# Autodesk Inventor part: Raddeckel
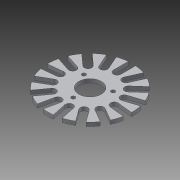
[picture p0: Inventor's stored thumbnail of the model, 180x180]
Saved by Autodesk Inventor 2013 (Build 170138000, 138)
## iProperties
Created: 2012-07
Part Number: Raddeckel
Material: Aluminium 6061
Document SubType Name: Modeling
Designer: rYan
Mass: 5.30786 g
Surface Area: 28.6162 cm^2
Volume: 1.95862 cm^3
Density: 2.71 g/cm^3
Author: rYan
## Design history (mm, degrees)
sketch "Skizze1"
  geometry: C1 r 22.5 at (0, 0); A1 r 22.5 centre (0, 0) between (2, 22.411) and (-2, 22.411) reference; 1 further point
  constraints: 2 centre point, 2 point on circle, 1 coincident, 4 other
extrude "Extrusion1" new body sketch "Skizze1" distance "d0" = 2; taper "d1" = 0 deg
sketch "Skizze2"
  geometry: L1 (-2, 22.5)-(2, 22.5); L2 (2, 22.5)-(2, 14.5); L3 (-2, 22.5)-(-2, 14.5); L4 (0, 31.5)-(0, -31.5); C1 r 12.5 at (0, 0); C2 r 22.5 at (0, 0); A1 r 2 centre (0, 14.5) between (-2, 14.5) and (2, 14.5); 2 further points
  constraints: 8 end point, 4 tangent, 3 centre point, 2 point on circle, 1 coincident, 1 parallel, 1 perpendicular, 1 other
  dimensions: "d2" = 25 diameter of C1; "d3" = 4 distance between parallel lines of L2 L3
extrude "Extrusion2" cut sketch "Skizze2" distance "d4" = 2; taper "d5" = 0 deg
pattern_circular "Runde Anordnung1" dims angle "d7" = 360 deg
sketch "Skizze3"
  geometry: 1 further point
hole "Bohrung1" sketch "Skizze3" at (0, 0) diameter "d9" = 8; stored, may be unused: countersink angle "d13" = 90 deg, drill point angle "d15" = 118 deg; dims "d10" = 6, "d11" = 4, "d12" = 2, "d14" = 8
sketch "Skizze5"
  geometry: L1 (0, 31.393)-(0, -31.482) reference; L2 (-31.5, 0)-(31.5, 0) reference; 2 further points
  constraints: 1 point on line
  dimensions: "d17" = 9 distance from line of L2 point (0, -9)
hole "Bohrung2" sketch "Skizze5" at (0, -9) diameter "d18" = 2.1; stored, may be unused: countersink angle "d22" = 90 deg, drill point angle "d24" = 118 deg; dims "d19" = 6, "d20" = 4, "d21" = 2, "d23" = 8
pattern_circular "Runde Anordnung2" dims angle "d26" = 360 deg
node "Volumenkörper1"
